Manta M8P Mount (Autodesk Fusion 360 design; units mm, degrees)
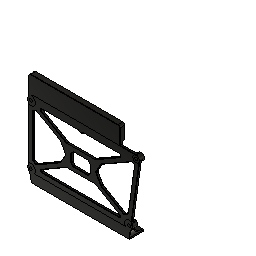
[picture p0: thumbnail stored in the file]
base_feature "Base Feature2"
base_feature "Base Feature1" bodies "Manta M8P Mount"
delete_face "DeleteFace1"
delete_face "DeleteFace2"
delete_face "DeleteFace3"
delete_face "DeleteFace4"
delete_face "DeleteFace5"
extrude "Extrude1" add of existing geometry blind 2
sketch "Sketch1" plane through (0, 0, 1.1227) normal (0, 0, 1) x axis (-1, 0, 0)
  line L1 (-131.6311, 113.097) -> (-131.6311, 16.45)
  line L2 (-135.0601, 116.526) -> (-131.6311, 113.097)
  line L3 (-299.0171, 116.526) -> (-135.0601, 116.526)
  line L4 (-301.5571, 113.986) -> (-299.0171, 116.526)
  line L5 (-301.5571, 16.069) -> (-301.5571, 113.986)
  line L6 (-299.2711, 13.783) -> (-301.5571, 16.069)
  line L7 (-134.2981, 13.783) -> (-299.2711, 13.783)
  line L8 (-131.6311, 16.45) -> (-134.2981, 13.783)
  line L9 (-295.6511, 67.661) -> (-296.6511, 67.661)
  line L10 (-296.6511, 66.961) -> (-295.6511, 66.961)
  line L11 (-299.9811, 67.661) -> (-300.6811, 67.661)
  line L12 (-300.6811, 66.961) -> (-299.9811, 66.961)
  line L13 (-295.6511, 59.021) -> (-296.6511, 59.021)
  line L14 (-296.6511, 58.321) -> (-295.6511, 58.321)
  line L15 (-299.9811, 59.021) -> (-300.6811, 59.021)
  line L16 (-300.6811, 58.321) -> (-299.9811, 58.321)
  circle C1 centre (-148.9097, 110.938) radius 0.55
  circle C2 centre (-153.9097, 110.938) radius 0.55
  circle C3 centre (-136.6311, 108.526) radius 1.65
  circle C4 centre (-145.4007, 97.351) radius 1
  circle C5 centre (-158.9427, 110.938) radius 0.55
  circle C6 centre (-163.9427, 110.938) radius 0.55
  circle C7 centre (-161.2927, 100.143) radius 0.4826
  circle C8 centre (-168.8957, 110.938) radius 0.55
  circle C9 centre (-163.8327, 100.143) radius 0.4826
  circle C10 centre (-160.0227, 93.212) radius 0.45
  circle C11 centre (-160.0227, 95.752) radius 0.45
  circle C12 centre (-145.4007, 87.851) radius 1
  circle C13 centre (-162.5627, 93.212) radius 0.45
  circle C14 centre (-160.0227, 90.672) radius 0.45
  circle C15 centre (-162.5627, 95.752) radius 0.45
  circle C16 centre (-168.1811, 95.741) radius 0.45
  circle C17 centre (-162.5627, 90.672) radius 0.45
  circle C18 centre (-168.1811, 93.201) radius 0.45
  circle C19 centre (-168.1811, 90.661) radius 0.45
  circle C20 centre (-169.3877, 100.143) radius 0.4826
  circle C21 centre (-173.8957, 110.938) radius 0.55
  circle C22 centre (-171.9277, 100.143) radius 0.4826
  circle C23 centre (-176.1377, 95.752) radius 0.45
  circle C24 centre (-178.9287, 110.938) radius 0.55
  circle C25 centre (-183.9287, 110.938) radius 0.55
  circle C26 centre (-177.4077, 100.143) radius 0.4826
  circle C27 centre (-179.9477, 100.143) radius 0.4826
  circle C28 centre (-184.2327, 95.752) radius 0.45
  circle C29 centre (-170.7211, 95.741) radius 0.45
  circle C30 centre (-176.1377, 93.212) radius 0.45
  circle C31 centre (-170.7211, 93.201) radius 0.45
  circle C32 centre (-176.1377, 90.672) radius 0.45
  circle C33 centre (-170.7211, 90.661) radius 0.45
  circle C34 centre (-178.6777, 93.212) radius 0.45
  circle C35 centre (-178.6777, 95.752) radius 0.45
  circle C36 centre (-178.6777, 90.672) radius 0.45
  circle C37 centre (-184.2327, 93.212) radius 0.45
  circle C38 centre (-184.2327, 90.672) radius 0.45
  circle C39 centre (-145.4007, 68.851) radius 1
  circle C40 centre (-145.4007, 78.351) radius 1
  circle C41 centre (-145.4007, 59.351) radius 1
  circle C42 centre (-152.7667, 53.28) radius 0.5
  circle C43 centre (-167.6991, 70.804) radius 0.15
  circle C44 centre (-167.6991, 71.804) radius 0.15
  circle C45 centre (-162.3651, 57.725) radius 0.4825
  circle C46 centre (-167.4451, 57.725) radius 0.4825
  circle C47 centre (-164.9051, 57.725) radius 0.4825
  circle C48 centre (-145.4007, 49.851) radius 1
  circle C49 centre (-152.7667, 50.74) radius 0.5
  circle C50 centre (-152.7667, 48.2) radius 0.5
  circle C51 centre (-155.5607, 46.93) radius 0.5
  circle C52 centre (-152.7667, 45.66) radius 0.5
  circle C53 centre (-160.6407, 46.93) radius 0.5
  circle C54 centre (-165.8061, 47.351) radius 0.45
  circle C55 centre (-158.1007, 46.93) radius 0.5
  circle C56 centre (-163.1807, 46.93) radius 0.5
  circle C57 centre (-165.8061, 45.351) radius 0.45
  circle C58 centre (-168.6991, 70.804) radius 0.15
  circle C59 centre (-168.6991, 71.804) radius 0.15
  circle C60 centre (-168.7687, 50.74) radius 0.5
  circle C61 centre (-168.7687, 53.28) radius 0.5
  circle C62 centre (-172.9061, 57.725) radius 0.4825
  circle C63 centre (-175.4461, 57.725) radius 0.4825
  circle C64 centre (-177.9861, 57.725) radius 0.4825
  circle C65 centre (-183.4471, 57.725) radius 0.4825
  circle C66 centre (-184.7707, 53.28) radius 0.5
  circle C67 centre (-168.7687, 48.2) radius 0.5
  circle C68 centre (-171.5627, 46.93) radius 0.5
  circle C69 centre (-168.7687, 45.66) radius 0.5
  circle C70 centre (-176.6427, 46.93) radius 0.5
  circle C71 centre (-174.1027, 46.93) radius 0.5
  circle C72 centre (-181.8061, 47.351) radius 0.45
  circle C73 centre (-184.7707, 50.74) radius 0.5
  circle C74 centre (-179.1827, 46.93) radius 0.5
  circle C75 centre (-184.7707, 45.66) radius 0.5
  circle C76 centre (-181.8061, 45.351) radius 0.45
  circle C77 centre (-188.8041, 112.601) radius 0.4572
  circle C78 centre (-191.3441, 112.601) radius 0.4572
  circle C79 centre (-193.8841, 112.601) radius 0.4572
  circle C80 centre (-194.0111, 108.537) radius 0.45
  circle C81 centre (-196.4241, 112.601) radius 0.4572
  circle C82 centre (-199.8611, 112.601) radius 0.4572
  circle C83 centre (-202.4011, 112.601) radius 0.4572
  circle C84 centre (-204.9411, 112.601) radius 0.4572
  circle C85 centre (-205.0681, 108.537) radius 0.45
  circle C86 centre (-194.0111, 103.457) radius 0.45
  circle C87 centre (-194.0111, 105.997) radius 0.45
  circle C88 centre (-185.5027, 100.143) radius 0.4826
  circle C89 centre (-188.0427, 100.143) radius 0.4826
  circle C90 centre (-186.7727, 95.752) radius 0.45
  circle C91 centre (-196.5511, 105.997) radius 0.45
  circle C92 centre (-196.5511, 108.537) radius 0.45
  circle C93 centre (-196.5511, 103.457) radius 0.45
  circle C94 centre (-205.0681, 105.997) radius 0.45
  circle C95 centre (-205.0681, 103.457) radius 0.45
  circle C96 centre (-207.4811, 112.601) radius 0.4572
  circle C97 centre (-210.8431, 112.601) radius 0.4572
  circle C98 centre (-207.6081, 108.537) radius 0.45
  circle C99 centre (-213.3831, 112.601) radius 0.4572
  circle C100 centre (-215.9231, 112.601) radius 0.4572
  circle C101 centre (-221.3311, 115.201) radius 0.45
  circle C102 centre (-216.0501, 108.537) radius 0.45
  circle C103 centre (-218.4631, 112.601) radius 0.4572
  circle C104 centre (-218.5901, 108.537) radius 0.45
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  dimension "d21" diameter = 10
  dimension "d22" diameter = 4.4
delete_face "DeleteFace6"
delete_face "DeleteFace7"
extrude "Extrude2" sketch "Sketch1" to an object
sketch "Sketch2" plane through (0, 6.5762, 0) normal (0, 1, 0) x axis (-1, 0, 0)
  line L1 (-142.3104, 14.4734) -> (-280.9517, 14.4734)
  line L2 (-133.2702, 102.4118) -> (-133.2702, 24.6401)
  line L3 (-138.4122, 116.8425) -> (-138.4122, 115.2718)
  line L4 (-272.0598, 116.8425) -> (-138.4122, 116.8425)
  line L5 (-236.1118, 64.1776) -> (-243.9334, 77.7249)
  line L6 (-236.1118, 62.6582) -> (-236.1118, 64.1776)
  line L7 (-243.9334, 49.1108) -> (-236.1118, 62.6582)
  line L8 (-278.5634, 29.1172) -> (-243.9334, 49.1108)
  line L9 (-198.3191, 56.8057) -> (-198.3191, 69.6247)
  line L10 (-201.5113, 53.6135) -> (-198.3191, 56.8057)
  line L11 (-223.6133, 53.6135) -> (-201.5113, 53.6135)
  line L12 (-226.8056, 56.8057) -> (-223.6133, 53.6135)
  line L13 (-226.8056, 69.6247) -> (-226.8056, 56.8057)
  line L14 (-223.6133, 72.817) -> (-226.8056, 69.6247)
  line L15 (-201.5113, 72.817) -> (-223.6133, 72.817)
  line L16 (-198.3191, 69.6247) -> (-201.5113, 72.817)
  line L17 (-189.0809, 64.1776) -> (-189.0809, 62.6582)
  line L18 (-181.2593, 77.7249) -> (-189.0809, 64.1776)
  line L19 (-144.7094, 98.827) -> (-181.2593, 77.7249)
  line L20 (-139.8267, 96.008) -> (-144.7094, 98.827)
  line L21 (-139.8267, 30.8277) -> (-139.8267, 96.008)
  line L22 (-144.7094, 28.0087) -> (-139.8267, 30.8277)
  line L23 (-181.2593, 49.1108) -> (-144.7094, 28.0087)
  line L24 (-189.0809, 62.6582) -> (-181.2593, 49.1108)
  line L25 (-190.5536, 46.9061) -> (-234.6391, 46.9061)
  line L26 (-152.0935, 24.7011) -> (-190.5536, 46.9061)
  line L27 (-152.8488, 21.8821) -> (-152.0935, 24.7011)
  line L28 (-272.3439, 21.8821) -> (-152.8488, 21.8821)
  line L29 (-273.0992, 24.7011) -> (-272.3439, 21.8821)
  line L30 (-234.6391, 46.9061) -> (-273.0992, 24.7011)
  line L31 (-151.9316, 105.4832) -> (-208.7048, 105.4832)
  line L32 (-151.1762, 102.6642) -> (-151.9316, 105.4832)
  line L33 (-191.3173, 79.4887) -> (-151.1762, 102.6642)
  line L34 (-233.8754, 79.4887) -> (-191.3173, 79.4887)
  line L35 (-216.6399, 105.4832) -> (-273.2612, 105.4832)
  line L36 (-297.1941, 116.5256) -> (-272.0598, 116.8425)
  line L37 (-290.0026, 24.6343) -> (-302.0827, 110.832)
  line L38 (-284.6151, 33.4368) -> (-294.2084, 101.8898)
  line L39 (-278.5634, 29.1172) -> (-284.6151, 33.4368)
  line L40 (-273.2612, 101.9882) -> (-233.8754, 79.4887)
  line L41 (-290.5608, 104.3613) -> (-243.9334, 77.7249)
  line L42 (-212.5623, 53.6135) -> (-212.5623, 72.817)
  line L43 (-198.3191, 63.2152) -> (-226.8056, 63.2152)
  line L44 (-212.5623, 63.2152) -> (-297.1311, 111.526)
  line L45 (-290.5608, 104.3613) -> (-294.2084, 101.8898)
  line L46 (-273.2612, 101.9882) -> (-273.2612, 105.4832)
  arc A1 centre (-286.6311, 18.526) radius 6.977 clockwise from (-290.0026, 24.6343) to (-280.9517, 14.4734)
  arc A2 centre (-136.6311, 18.526) radius 6.9769 clockwise from (-142.3104, 14.4734) to (-133.2702, 24.6401)
  arc A3 centre (-136.6311, 108.526) radius 6.977 clockwise from (-133.2702, 102.4118) to (-138.4122, 115.2718)
  arc A4 centre (-212.6723, 108.526) radius 5 clockwise from (-208.7048, 105.4832) to (-216.6399, 105.4832)
  circle C1 centre (-297.1311, 111.526) radius 2.2
  circle C2 centre (-297.1311, 111.526) radius 5
  point P17 (-278.5634, 29.1172)
  point P52 (-278.5634, 29.1172)
  point P44 (-233.8754, 79.4887)
  point P53 (-233.8754, 79.4887)
  point P13 (-243.9334, 77.7249)
  point P54 (-243.9334, 77.7249)
  point P55 (-212.5623, 72.817)
  point P56 (-212.5623, 53.6135)
  point P57 (-226.8056, 63.2152)
  point P58 (-198.3191, 63.2152)
  point P59 (-212.5623, 63.2152)
  point P49 (-297.1311, 111.526)
  point P60 (-297.1311, 111.526)
  point P61 (-212.5623, 63.2152)
  point P62 (-297.1941, 116.5256)
  point P50 (-302.0827, 110.832)
  point P48 (-272.0598, 116.8425)
  point P12 (-272.0598, 116.8425)
  point P65 (-294.9023, 106.8414)
  point P45 (-273.2612, 105.4832)
  point P66 (-273.2612, 105.4832)
  point P63 (-294.2084, 101.8898)
  point P64 (-290.5608, 104.3613)
  coincident P17 P52
  coincident P44 P53
  coincident P13 P54
  parallel L40 L41
  midpoint L15 P55
  midpoint L11 P56
  midpoint L13 P57
  midpoint L9 P58
  midpoint L42 P59
  coincident P49 P60
  coincident P59 P61
  parallel L41 L44
  coincident C2 P62
  tangent L36 C2
  tangent C2 L37
  coincident C2 P50
  coincident L4 P48
  coincident P12 P48
  coincident L38 P65
  coincident L41 P65
  coincident P45 P66
  perpendicular L35 L46
  dimension "d29" distance L37 L38 = 6.557
  dimension "d31" distance P63 P65 = 5
  dimension "d32" distance P64 P65 = 5 (= "d31")
  dimension "d33" angle L38 L39 = 133.496 (= "Angular Dimension-2")
extrude "Extrude3" add sketch "Sketch2" profile of A1 L1 A2 L2 A3 L3 L4 L5 L6 L7 L8 L9 L10 L11 L12 L13 L14 L15 L16 L17 L18 L19 L20 L21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 against normal blind 3.407
extrude "Extrude4" cut sketch "Sketch2" profile of L5 L6 L7 L8 L38 L39 L41 L45 against normal blind 3.407
fillet "Fillet1" radius 2
delete_face "DeleteFace8"
chamfer "Chamfer1" distance 0.75 distance 0.4 distance 0.5 distance 0.5
delete_face "DeleteFace9"
named bodies: "Manta M8P Mount"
